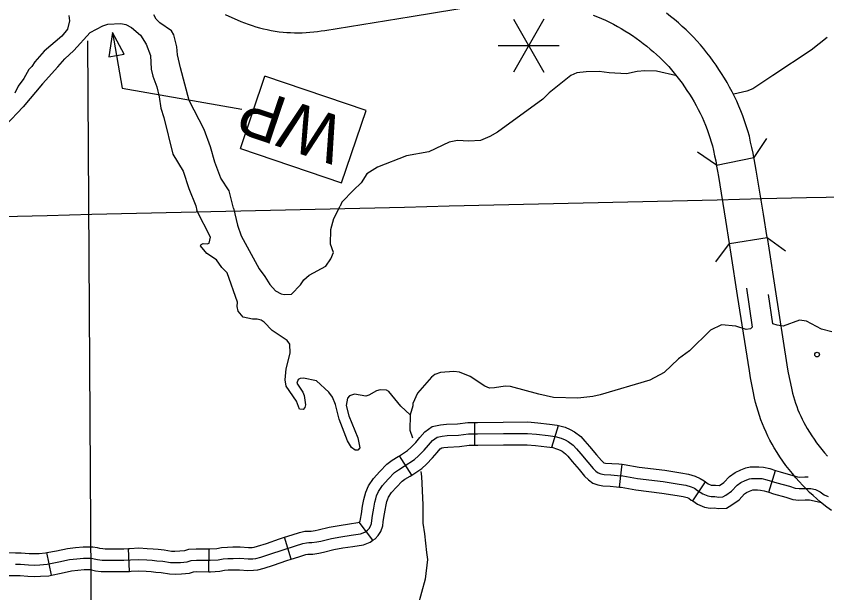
# Model space of a CAD drawing. Extents: x -19 to 366, y -4 to 359.
# Drawn here: x 132.38 to 133.386, y 199.204 to 199.92 of the extents above; entities that cross this region are included whole.
import ezdxf

# ---------------------------------------------------------------- set-up
doc = ezdxf.new("R2010")
doc.units = 0
for name, color, linetype in [('Level 10', 7, 'Continuous'), ('Level 32', 7, 'Continuous'), ('Level 35', 7, 'Continuous'), ('Level 37', 7, 'Continuous'), ('Level 48', 7, 'Continuous'), ('Level 5', 7, 'Continuous'), ('Level 57', 7, 'Continuous'), ('Level 60', 7, 'Continuous'), ('Level 9', 7, 'Continuous')]:
    doc.layers.add(name, color=color, linetype=linetype)

msp = doc.modelspace()

# ---------------------------------------------------------------- linework, layer by layer
at = {"layer": 'Level 10'}
for p, q in [((133.2493, 199.7353), (133.2957, 199.7446)), ((133.2652, 199.6381), (133.312, 199.6454))]:
    msp.add_line(p, q, dxfattribs=at)
for points in [[(132.639, 199.9222), (132.6587, 199.9136), (132.6633, 199.9118), (132.6679, 199.9101), (132.6726, 199.9085), (132.6772, 199.907), (132.682, 199.9057), (132.6867, 199.9045), (132.6915, 199.9034), (132.6963, 199.9024), (132.7012, 199.9016), (132.7061, 199.9008), (132.711, 199.9003), (132.7158, 199.8999), (132.7205, 199.8996), (132.7253, 199.8994), (132.7301, 199.8994), (132.7348, 199.8995), (132.7396, 199.8997), (132.7443, 199.9), (132.7491, 199.9005), (132.7538, 199.901), (132.7585, 199.9017), (132.7628, 199.9024), (132.87, 199.9198), (132.9784, 199.9375)], [(133.0962, 199.9215), (133.1013, 199.9194), (133.1063, 199.9172), (133.1113, 199.9149), (133.1163, 199.9125), (133.1212, 199.91), (133.1261, 199.9074), (133.1309, 199.9047), (133.1356, 199.9018), (133.1403, 199.8989), (133.1449, 199.8959), (133.1494, 199.8927), (133.1539, 199.8895), (133.1583, 199.8862), (133.1627, 199.8827), (133.167, 199.8793), (133.171, 199.8759), (133.1749, 199.8724), (133.1788, 199.8688), (133.1826, 199.8651), (133.1863, 199.8613), (133.1899, 199.8574), (133.1934, 199.8535), (133.1968, 199.8494), (133.2001, 199.8453), (133.2033, 199.8411), (133.2065, 199.8369), (133.2095, 199.8325), (133.2125, 199.8279), (133.2157, 199.8232), (133.2185, 199.8186), (133.2213, 199.8139), (133.224, 199.8092), (133.2265, 199.8044), (133.229, 199.7995), (133.2313, 199.7947), (133.2334, 199.7897), (133.2355, 199.7847), (133.2375, 199.7796), (133.2394, 199.7745), (133.2411, 199.7694), (133.2427, 199.7642), (133.2441, 199.7593), (133.2455, 199.7533), (133.2469, 199.7468), (133.2483, 199.7404), (133.2493, 199.7353)], [(133.2957, 199.7446), (133.2947, 199.75), (133.2932, 199.7569), (133.2916, 199.7638), (133.29, 199.7711), (133.2881, 199.7777), (133.2861, 199.784), (133.2841, 199.7901), (133.2818, 199.7963), (133.2795, 199.8024), (133.277, 199.8084), (133.2743, 199.8144), (133.2715, 199.8203), (133.2686, 199.8262), (133.2655, 199.8319), (133.2623, 199.8376), (133.259, 199.8432), (133.2555, 199.8488), (133.2521, 199.854), (133.2487, 199.8591), (133.245, 199.8644), (133.2412, 199.8695), (133.2373, 199.8746), (133.2333, 199.8796), (133.2292, 199.8845), (133.2249, 199.8893), (133.2206, 199.894), (133.2161, 199.8986), (133.2115, 199.903), (133.2068, 199.9074), (133.202, 199.9117), (133.1971, 199.9158), (133.1922, 199.9197), (133.1872, 199.9237)], [(133.312, 199.6454), (133.3075, 199.6743), (133.2986, 199.729), (133.2974, 199.7361), (133.2961, 199.7431), (133.2957, 199.7446)], [(133.2652, 199.6381), (133.2608, 199.6669), (133.252, 199.7211), (133.2508, 199.7275), (133.2496, 199.734), (133.2493, 199.7353)], [(133.3861, 199.3109), (133.3826, 199.3136), (133.378, 199.3173), (133.3736, 199.3211), (133.3692, 199.325), (133.3649, 199.329), (133.3608, 199.3331), (133.3563, 199.3377), (133.3519, 199.3424), (133.3476, 199.3473), (133.3434, 199.3523), (133.3394, 199.3574), (133.3355, 199.3625), (133.3316, 199.3678), (133.328, 199.3732), (133.3245, 199.3786), (133.321, 199.3843), (133.3183, 199.3891), (133.3156, 199.394), (133.3131, 199.3989), (133.3107, 199.4039), (133.3085, 199.409), (133.3064, 199.4141), (133.3044, 199.4193), (133.3025, 199.4246), (133.3008, 199.4299), (133.2992, 199.4352), (133.2978, 199.4405), (133.2965, 199.446), (133.2946, 199.4545), (133.293, 199.4629), (133.2914, 199.4714), (133.29, 199.4798), (133.2753, 199.5734), (133.2673, 199.6248), (133.2652, 199.6381)], [(133.312, 199.6454), (133.3141, 199.6321), (133.3221, 199.5807), (133.3367, 199.4874), (133.338, 199.4796), (133.3395, 199.4718), (133.341, 199.464), (133.3426, 199.4564), (133.3436, 199.4522), (133.3448, 199.4481), (133.346, 199.4439), (133.3473, 199.4398), (133.3488, 199.4357), (133.3503, 199.4317), (133.352, 199.4277), (133.3538, 199.4237), (133.3556, 199.4198), (133.3576, 199.4159), (133.3596, 199.4121), (133.3618, 199.4084), (133.3645, 199.4039), (133.3674, 199.3994), (133.3704, 199.395), (133.3735, 199.3907), (133.3768, 199.3864), (133.3801, 199.3823), (133.3835, 199.3782), (133.387, 199.3742)], [(133.3919, 199.3066), (133.3861, 199.3109)]]:
    msp.add_lwpolyline(points, dxfattribs=at)
at = {"layer": 'Level 32'}
for p, q in [((132.9493, 199.3876), (132.949, 199.416)), ((133.0449, 199.385), (133.0529, 199.4122)), ((132.871, 199.3506), (132.8555, 199.3744)), ((133.1289, 199.3356), (133.1319, 199.3639)), ((133.314, 199.3293), (133.3224, 199.3564)), ((133.2199, 199.3184), (133.2354, 199.3421)), ((132.8227, 199.2696), (132.8057, 199.2923)), ((132.7213, 199.2462), (132.7128, 199.2733)), ((132.4236, 199.2264), (132.4179, 199.2543)), ((132.5205, 199.231), (132.5192, 199.2594)), ((132.6191, 199.2306), (132.6194, 199.259))]:
    msp.add_line(p, q, dxfattribs=at)
for points in [[(132.8555, 199.3744), (132.8656, 199.381), (132.8695, 199.3846), (132.8758, 199.3909), (132.8808, 199.397), (132.8869, 199.4042), (132.8963, 199.4109), (132.9064, 199.4131), (132.9141, 199.4137), (132.9276, 199.4142), (132.9403, 199.4159), (132.949, 199.416)], [(132.949, 199.416), (132.9524, 199.416), (132.9844, 199.4164), (133.0151, 199.4165), (133.0272, 199.4155), (133.0419, 199.4137), (133.0516, 199.4126), (133.0529, 199.4122)], [(133.0529, 199.4122), (133.0612, 199.4098), (133.0674, 199.4072), (133.0729, 199.4041), (133.0808, 199.3984), (133.0859, 199.3927), (133.0917, 199.386), (133.1004, 199.3755), (133.1064, 199.3685), (133.1084, 199.3664), (133.109, 199.366), (133.1093, 199.3659), (133.1115, 199.3655), (133.1191, 199.3651), (133.1279, 199.3643), (133.1319, 199.3639)], [(132.8212, 199.2943), (132.8223, 199.3003), (132.8237, 199.3095), (132.8251, 199.3168), (132.8263, 199.3212), (132.8271, 199.3248), (132.8297, 199.3301), (132.8346, 199.3377), (132.8417, 199.3453), (132.8496, 199.3536), (132.8543, 199.3572), (132.8615, 199.3614), (132.8744, 199.3698), (132.8793, 199.3744), (132.8863, 199.3814), (132.8916, 199.3878), (132.8966, 199.3936), (132.9022, 199.3977), (132.9085, 199.399), (132.915, 199.3995), (132.9288, 199.4001), (132.9413, 199.4017), (132.9525, 199.4018), (132.9846, 199.4022), (133.0146, 199.4023), (133.0258, 199.4014), (133.0403, 199.3996), (133.0488, 199.3986), (133.0565, 199.3963), (133.0612, 199.3944), (133.0652, 199.3921), (133.0712, 199.3877), (133.0753, 199.3833), (133.0809, 199.3768), (133.0895, 199.3664), (133.0959, 199.3588), (133.0992, 199.3556), (133.1023, 199.3534), (133.1055, 199.3522), (133.1098, 199.3514), (133.1181, 199.351), (133.1264, 199.3502), (133.1328, 199.3495), (133.1512, 199.3465), (133.1832, 199.3424), (133.2027, 199.3394), (133.2112, 199.338), (133.2178, 199.3361), (133.2219, 199.3342), (133.2258, 199.3314), (133.2324, 199.3271), (133.2385, 199.3246), (133.2426, 199.3238), (133.2472, 199.3239), (133.2523, 199.3232), (133.2572, 199.3236), (133.2607, 199.3256), (133.2679, 199.3306), (133.2747, 199.338), (133.2795, 199.3414), (133.2849, 199.3438), (133.2901, 199.3458), (133.2928, 199.3464), (133.2971, 199.3465), (133.301, 199.3464), (133.3057, 199.3461), (133.3118, 199.3448), (133.3243, 199.341), (133.3397, 199.3366), (133.3467, 199.3342), (133.3518, 199.3338), (133.3592, 199.334), (133.3663, 199.334), (133.3722, 199.3327), (133.3779, 199.3297), (133.3828, 199.3261), (133.3878, 199.3241)], [(132.871, 199.3506), (132.8832, 199.3586), (132.8892, 199.3642), (132.8968, 199.3718), (132.9025, 199.3787), (132.9063, 199.3831), (132.9081, 199.3844), (132.9105, 199.3849), (132.9158, 199.3853), (132.93, 199.3859), (132.9423, 199.3875), (132.9493, 199.3876)], [(132.9493, 199.3876), (132.9527, 199.3876), (132.9847, 199.388), (133.014, 199.3881), (133.0244, 199.3872), (133.0386, 199.3855), (133.0459, 199.3847), (133.0449, 199.385)], [(133.0449, 199.385), (133.0518, 199.3829), (133.055, 199.3816), (133.0574, 199.3802), (133.0617, 199.3771), (133.0646, 199.3739), (133.07, 199.3676), (133.0786, 199.3573), (133.0855, 199.3491), (133.0901, 199.3447), (133.0956, 199.3407), (133.1018, 199.3384), (133.1081, 199.3373), (133.117, 199.3368), (133.125, 199.336), (133.1289, 199.3356)], [(132.8057, 199.2923), (132.8063, 199.2928), (132.8067, 199.2932), (132.8069, 199.2935), (132.8071, 199.2959), (132.8083, 199.3026), (132.8097, 199.3119), (132.8112, 199.3201), (132.8126, 199.3247), (132.8137, 199.3295), (132.8173, 199.3371), (132.8234, 199.3464), (132.8314, 199.3551), (132.8401, 199.3642), (132.8464, 199.369), (132.8541, 199.3735), (132.8555, 199.3744)], [(133.1319, 199.3639), (133.1347, 199.3636), (133.1533, 199.3605), (133.1852, 199.3565), (133.205, 199.3535), (133.2144, 199.3518), (133.2228, 199.3494), (133.229, 199.3465), (133.2338, 199.3432), (133.2354, 199.3421)], [(133.2354, 199.3421), (133.239, 199.3397), (133.2427, 199.3382), (133.2437, 199.338), (133.2481, 199.3382), (133.2528, 199.3375), (133.2528, 199.3375), (133.253, 199.3376), (133.2585, 199.3414), (133.2653, 199.3487), (133.2725, 199.3538), (133.2795, 199.3569), (133.2858, 199.3594), (133.2909, 199.3606), (133.2971, 199.3608), (133.3017, 199.3606), (133.3077, 199.3602), (133.3154, 199.3586), (133.3224, 199.3564)], [(133.3224, 199.3564), (133.3283, 199.3546), (133.3439, 199.3502), (133.3497, 199.3482), (133.3521, 199.348), (133.359, 199.3482), (133.363, 199.3482)], [(132.8227, 199.2696), (132.8253, 199.2715), (132.8292, 199.2756), (132.8324, 199.2806), (132.835, 199.2874), (132.8353, 199.2926), (132.8363, 199.2979), (132.8377, 199.3071), (132.8389, 199.3135), (132.8401, 199.3177), (132.8406, 199.32), (132.8421, 199.3231), (132.8459, 199.3289), (132.8521, 199.3356), (132.8591, 199.343), (132.8622, 199.3454), (132.869, 199.3493), (132.871, 199.3506)], [(133.1289, 199.3356), (133.1309, 199.3354), (133.1492, 199.3324), (133.1812, 199.3283), (133.2005, 199.3254), (133.208, 199.3241), (133.2128, 199.3228), (133.2147, 199.3218), (133.2179, 199.3196), (133.2199, 199.3184)], [(133.2199, 199.3184), (133.2257, 199.3145), (133.2344, 199.3109), (133.2414, 199.3095), (133.2464, 199.3097), (133.2518, 199.3089), (133.2615, 199.3096), (133.2684, 199.3136), (133.2772, 199.3198), (133.2841, 199.3272), (133.2866, 199.329), (133.2903, 199.3306), (133.2943, 199.3322), (133.2947, 199.3323), (133.2971, 199.3323), (133.3003, 199.3322), (133.3037, 199.332), (133.3083, 199.331), (133.314, 199.3293)], [(133.314, 199.3293), (133.3202, 199.3273), (133.3354, 199.323), (133.3438, 199.3202), (133.3514, 199.3195), (133.3594, 199.3198), (133.3647, 199.3198), (133.3778, 199.3168)], [(132.3787, 199.24), (132.3852, 199.24), (132.3949, 199.2392), (132.4026, 199.2389), (132.4089, 199.2391), (132.4181, 199.2398), (132.4328, 199.2428), (132.4458, 199.2456), (132.4548, 199.2467), (132.4634, 199.2474), (132.469, 199.2475), (132.4733, 199.2475), (132.4767, 199.2468), (132.4807, 199.2456), (132.4863, 199.2451), (132.4899, 199.245), (132.4974, 199.245), (132.506, 199.2449), (132.5135, 199.2449), (132.5216, 199.2453), (132.5321, 199.2458), (132.5419, 199.2453), (132.5485, 199.2451), (132.5545, 199.2443), (132.5616, 199.2436), (132.5713, 199.2421), (132.5769, 199.2419), (132.5839, 199.2422), (132.592, 199.2429), (132.5969, 199.2447), (132.6035, 199.245), (132.6205, 199.2448), (132.6306, 199.2455), (132.6366, 199.2467), (132.6424, 199.247), (132.6491, 199.2472), (132.6575, 199.2473), (132.6679, 199.2465), (132.6734, 199.2466), (132.6774, 199.247), (132.6834, 199.2485), (132.6948, 199.2522), (132.7112, 199.2579), (132.7265, 199.2627), (132.7355, 199.2655), (132.74, 199.2666), (132.743, 199.2667), (132.7469, 199.2667), (132.7531, 199.2676), (132.758, 199.2685), (132.7712, 199.272), (132.7829, 199.2741), (132.7956, 199.2761), (132.8073, 199.2777), (132.8125, 199.2797), (132.8158, 199.2822), (132.8179, 199.2844), (132.8197, 199.2871), (132.821, 199.2905), (132.8212, 199.2943)], [(132.7128, 199.2733), (132.7223, 199.2762), (132.7316, 199.2791), (132.738, 199.2808), (132.7428, 199.2809), (132.7459, 199.2809), (132.7508, 199.2816), (132.7548, 199.2824), (132.7681, 199.2859), (132.7806, 199.2881), (132.7935, 199.2901), (132.8037, 199.2915), (132.8056, 199.2922), (132.8057, 199.2923)], [(132.6194, 199.259), (132.6201, 199.259), (132.6287, 199.2596), (132.6348, 199.2608), (132.6419, 199.2612), (132.6487, 199.2614), (132.6579, 199.2615), (132.6682, 199.2607), (132.6725, 199.2608), (132.675, 199.261), (132.6794, 199.2622), (132.6903, 199.2657), (132.7067, 199.2714), (132.7128, 199.2733)], [(132.7213, 199.2462), (132.7308, 199.2491), (132.7394, 199.2518), (132.742, 199.2525), (132.7432, 199.2525), (132.7479, 199.2525), (132.7554, 199.2536), (132.7612, 199.2547), (132.7742, 199.2581), (132.7853, 199.2601), (132.7976, 199.262), (132.8108, 199.2638), (132.8194, 199.2671), (132.8227, 199.2696)], [(132.321, 199.2556), (132.3254, 199.2556), (132.3482, 199.2542), (132.3662, 199.2543), (132.3788, 199.2542), (132.3858, 199.2542), (132.3958, 199.2534), (132.4027, 199.2531), (132.4081, 199.2533), (132.4161, 199.2539), (132.4179, 199.2543)], [(132.4179, 199.2543), (132.4298, 199.2567), (132.4435, 199.2596), (132.4533, 199.2608), (132.4628, 199.2616), (132.4689, 199.2617), (132.4747, 199.2617), (132.4801, 199.2606), (132.4833, 199.2597), (132.4871, 199.2593), (132.4902, 199.2592), (132.4974, 199.2592), (132.506, 199.2591), (132.5132, 199.2591), (132.5192, 199.2594)], [(132.5192, 199.2594), (132.521, 199.2595), (132.5321, 199.2601), (132.5425, 199.2595), (132.5497, 199.2592), (132.5561, 199.2584), (132.5634, 199.2577), (132.5726, 199.2562), (132.5768, 199.2561), (132.5829, 199.2564), (132.5889, 199.2569), (132.5941, 199.2588), (132.6033, 199.2592), (132.6194, 199.259)], [(132.6191, 199.2306), (132.6209, 199.2306), (132.6324, 199.2313), (132.6384, 199.2325), (132.643, 199.2328), (132.6494, 199.233), (132.657, 199.2331), (132.6675, 199.2322), (132.6742, 199.2324), (132.6798, 199.2329), (132.6874, 199.2349), (132.6992, 199.2387), (132.7156, 199.2444), (132.7213, 199.2462)], [(132.4236, 199.2264), (132.4357, 199.2289), (132.4482, 199.2316), (132.4562, 199.2326), (132.4641, 199.2332), (132.4691, 199.2333), (132.4719, 199.2333), (132.4733, 199.233), (132.478, 199.2316), (132.4854, 199.231), (132.4897, 199.2308), (132.4973, 199.2308), (132.5059, 199.2307), (132.5138, 199.2307), (132.5205, 199.231)], [(132.3208, 199.2272), (132.3245, 199.2272), (132.3474, 199.2258), (132.3662, 199.2259), (132.3786, 199.2258), (132.3847, 199.2258), (132.394, 199.2251), (132.4025, 199.2247), (132.4097, 199.2249), (132.4201, 199.2257), (132.4236, 199.2264)], [(132.5205, 199.231), (132.5223, 199.2311), (132.5321, 199.2316), (132.5412, 199.2311), (132.5474, 199.2309), (132.5529, 199.2302), (132.5598, 199.2295), (132.5699, 199.2279), (132.577, 199.2277), (132.5848, 199.228), (132.595, 199.2289), (132.5997, 199.2306), (132.6038, 199.2308), (132.6191, 199.2306)]]:
    msp.add_lwpolyline(points, dxfattribs=at)
at = {"layer": 'Level 35'}
for points in [[(132.3956, 199.8538), (132.389, 199.8427), (132.3823, 199.8332), (132.3779, 199.8247)], [(132.4125, 199.8362), (132.3884, 199.8074), (132.3664, 199.7844), (132.3471, 199.7583), (132.3316, 199.7346), (132.314, 199.7165), (132.3051, 199.7057), (132.2812, 199.6857), (132.2703, 199.6779), (132.2662, 199.676), (132.2571, 199.6743), (132.2496, 199.6716)], [(132.869, 199.4255), (132.8685, 199.4061), (132.8716, 199.3967)], [(132.882, 199.355), (132.883, 199.3487), (132.8847, 199.3138), (132.8847, 199.2907), (132.8868, 199.2778), (132.8891, 199.2544), (132.8904, 199.2457), (132.8877, 199.2213), (132.8784, 199.1882), (132.8782, 199.1825), (132.8809, 199.1761), (132.878, 199.1666), (132.8537, 199.1279), (132.8467, 199.1141), (132.8417, 199.1004), (132.8306, 199.0827), (132.808, 199.0524), (132.8037, 199.0429), (132.7962, 199.0143), (132.7863, 198.9933), (132.7837, 198.9689), (132.7846, 198.9591), (132.7873, 198.9458)]]:
    msp.add_lwpolyline(points, dxfattribs=at)
at = {"layer": 'Level 37'}
for points in [[(133.3115, 199.7682), (133.2957, 199.7446)], [(133.2493, 199.7353), (133.2257, 199.7511)], [(133.2485, 199.6152), (133.2652, 199.6381)], [(133.312, 199.6454), (133.335, 199.6287)]]:
    msp.add_lwpolyline(points, dxfattribs=at)
at = {"layer": 'Level 48'}
for p, q in [((133.035, 199.9163), (132.9971, 199.8507)), ((132.9971, 199.9163), (133.035, 199.8507)), ((132.9782, 199.8835), (133.054, 199.8835))]:
    msp.add_line(p, q, dxfattribs=at)
at = {"layer": 'Level 5'}
msp.add_lwpolyline([(132.4737, 199.0864), (132.4687, 199.8893)], dxfattribs=at)
at = {"layer": 'Level 57'}
for p, q in [((132.6582, 199.7558), (132.6886, 199.8455)), ((132.8142, 199.8029), (132.6886, 199.8455)), ((132.7838, 199.7132), (132.8142, 199.8029)), ((132.6582, 199.7558), (132.7838, 199.7132))]:
    msp.add_line(p, q, dxfattribs=at)
msp.add_lwpolyline([(132.4947, 199.8694), (132.5137, 199.8728), (132.4992, 199.8997)], close=True, dxfattribs=at)
msp.add_lwpolyline([(132.4992, 199.8997), (132.5113, 199.8306), (132.6598, 199.8046)], dxfattribs=at)
msp.add_circle((133.3741, 199.5001), 0.00284, dxfattribs=at)
at = {"layer": 'Level 60'}
for points in [[(139.4406, 1.5315), (139.2511, 10.1473), (139.0608, 18.7633), (138.8699, 27.3793), (138.6784, 35.9956), (138.4861, 44.6119), (138.2932, 53.2285), (138.0997, 61.8451), (137.9055, 70.4619), (137.7106, 79.0789), (137.5151, 87.6959), (137.319, 96.3132), (137.1221, 104.9306), (136.9247, 113.5481), (136.7265, 122.1658), (136.5278, 130.7836), (136.3283, 139.4016), (136.1282, 148.0197), (135.9275, 156.6379), (135.7261, 165.2564), (135.5241, 173.8749), (135.3214, 182.4936), (135.1181, 191.1125), (134.9141, 199.7315), (134.7095, 208.3506), (134.5043, 216.9699), (134.2984, 225.5894), (134.0919, 234.209), (133.8847, 242.8288), (133.6769, 251.4487), (133.4685, 260.0687), (133.2594, 268.6889), (133.0497, 277.3093), (132.8393, 285.9298), (132.6283, 294.5504), (132.4167, 303.1713), (132.2044, 311.7922), (131.9916, 320.4133), (131.778, 329.0346), (131.5639, 337.656), (131.3491, 346.2776)], [(0, 198.1326), (7.1014, 198.137), (14.2028, 198.1503), (21.3042, 198.1724), (28.4055, 198.2034), (35.5068, 198.2433), (42.6081, 198.292), (49.7092, 198.3496), (56.8103, 198.4161), (63.9113, 198.4913), (71.0123, 198.5755), (78.1131, 198.6685), (85.2137, 198.7704), (92.3143, 198.8811), (99.4147, 199.0007), (106.5149, 199.1291), (113.615, 199.2664), (120.7149, 199.4126), (127.8146, 199.5676), (134.9141, 199.7315), (142.0135, 199.9042), (149.1125, 200.0858), (156.2114, 200.2762), (163.31, 200.4755), (170.4084, 200.6837), (177.5065, 200.9007), (184.6043, 201.1265), (191.7018, 201.3612), (198.799, 201.6048), (205.896, 201.8572), (212.9926, 202.1185), (220.0888, 202.3886), (227.1848, 202.6676), (234.2803, 202.9554), (241.3755, 203.2521), (248.4704, 203.5576), (255.5648, 203.872), (262.6589, 204.1952), (269.7525, 204.5273), (276.8457, 204.8682), (283.9385, 205.218), (291.0309, 205.5766), (298.1228, 205.9441), (305.2142, 206.3204), (312.3051, 206.7056), (319.3956, 207.0996), (326.4856, 207.5024), (333.5751, 207.9141), (340.664, 208.3347)], [(0, 189.5162), (7.1121, 189.5206), (14.2243, 189.5339), (21.3364, 189.556), (28.4484, 189.5869), (35.5605, 189.6267), (42.6725, 189.6754), (49.7844, 189.7329), (56.8962, 189.7992), (64.0079, 189.8744), (71.1196, 189.9584), (78.2311, 190.0512), (85.3425, 190.1529), (92.4538, 190.2635), (99.5649, 190.3829), (106.6759, 190.5111), (113.7867, 190.6482), (120.8974, 190.7941), (128.0078, 190.9489), (135.1181, 191.1125), (142.2282, 191.2849), (149.338, 191.4662), (156.4476, 191.6563), (163.5569, 191.8553), (170.666, 192.0631), (177.7749, 192.2798), (184.8835, 192.5053), (191.9917, 192.7396), (199.0997, 192.9828), (206.2074, 193.2348), (213.3147, 193.4956), (220.4218, 193.7653), (227.5285, 194.0438), (234.6348, 194.3312), (241.7408, 194.6274), (248.8464, 194.9324), (255.9516, 195.2463), (263.0564, 195.569), (270.1608, 195.9005), (277.2648, 196.2409), (284.3683, 196.5901), (291.4715, 196.9481), (298.5741, 197.315), (305.6763, 197.6907), (312.7781, 198.0753), (319.8793, 198.4686), (326.9801, 198.8708), (334.0804, 199.2818), (341.1801, 199.7017)]]:
    msp.add_spline(points, degree=3, dxfattribs=at)
at = {"layer": 'Level 9'}
for points in [[(132.4449, 199.9209), (132.4458, 199.9141), (132.4433, 199.9038), (132.4362, 199.8954), (132.4146, 199.8765), (132.403, 199.8634), (132.3993, 199.8577), (132.3956, 199.8538)], [(132.6496, 199.6817), (132.6443, 199.7033), (132.6339, 199.7191), (132.6264, 199.7387), (132.6211, 199.758), (132.6132, 199.7795), (132.5945, 199.8156), (132.5837, 199.8561), (132.58, 199.872), (132.5791, 199.8822), (132.5755, 199.8969), (132.5724, 199.9018), (132.5582, 199.9119), (132.5536, 199.9164), (132.5505, 199.9216)], [(132.4125, 199.8362), (132.4315, 199.857), (132.4401, 199.8673), (132.4513, 199.8774), (132.4714, 199.8997), (132.4871, 199.9082), (132.4935, 199.9102), (132.5098, 199.9108), (132.5159, 199.9098), (132.5227, 199.9061), (132.5339, 199.8964), (132.5412, 199.8855), (132.5464, 199.8711), (132.5474, 199.8541), (132.5494, 199.8457), (132.5545, 199.8325), (132.5574, 199.8201), (132.5591, 199.806), (132.5631, 199.7943), (132.574, 199.7486), (132.5872, 199.7279), (132.5939, 199.706), (132.6026, 199.6845), (132.6038, 199.6788)], [(133.3867, 199.8936), (133.3669, 199.8777)], [(133.3669, 199.8777), (133.3193, 199.8463), (133.2942, 199.83), (133.2867, 199.8269), (133.2707, 199.8234)], [(133.2, 199.8462), (133.1746, 199.8519), (133.1602, 199.8524), (133.1508, 199.8515), (133.1376, 199.8487), (133.116, 199.8499), (133.1035, 199.8513), (133.0876, 199.851), (133.0759, 199.8497), (133.0684, 199.8466), (133.0414, 199.825), (133.0336, 199.8169), (132.9774, 199.7763), (132.9677, 199.7708), (132.956, 199.7657), (132.9417, 199.7648), (132.9276, 199.7657), (132.9174, 199.7637), (132.8919, 199.7515), (132.8643, 199.7466), (132.8282, 199.7328), (132.8151, 199.7243), (132.8081, 199.7132), (132.7984, 199.7043)], [(132.7984, 199.7043), (132.7842, 199.6893), (132.782, 199.6844)], [(132.6119, 199.6378), (132.6168, 199.6375), (132.6195, 199.6383), (132.6209, 199.6459), (132.6038, 199.6788)], [(132.6496, 199.6817), (132.6543, 199.6608), (132.659, 199.6473), (132.6812, 199.6067), (132.6885, 199.5969), (132.6948, 199.5872), (132.7017, 199.5793), (132.7089, 199.5753), (132.7123, 199.5746), (132.7214, 199.5751), (132.7329, 199.5867), (132.737, 199.5928), (132.7433, 199.5986), (132.7643, 199.6099), (132.7702, 199.6188), (132.7735, 199.6268), (132.7699, 199.6373), (132.7704, 199.6552), (132.7743, 199.6689), (132.782, 199.6844)], [(132.869, 199.4255), (132.8571, 199.4359), (132.8424, 199.4542), (132.8394, 199.4561), (132.8318, 199.4563), (132.8269, 199.4551), (132.8175, 199.4496), (132.8138, 199.4484), (132.7998, 199.4509), (132.7937, 199.4489), (132.7911, 199.4462), (132.7894, 199.437), (132.7926, 199.4242), (132.804, 199.3967), (132.8065, 199.3842), (132.8039, 199.3815), (132.8005, 199.3815), (132.7959, 199.3848), (132.7912, 199.3931), (132.7806, 199.4198), (132.7761, 199.438), (132.7726, 199.4474), (132.768, 199.4534), (132.7526, 199.4675), (132.7363, 199.471), (132.7322, 199.4706), (132.7299, 199.469), (132.7281, 199.4645), (132.7355, 199.4536), (132.7374, 199.4491), (132.7391, 199.4377), (132.738, 199.4343), (132.7362, 199.432), (132.7313, 199.4323), (132.7277, 199.4421), (132.7149, 199.4608), (132.7137, 199.4688), (132.715, 199.4824), (132.7199, 199.5019), (132.7194, 199.5132), (132.7163, 199.5174), (132.6976, 199.5299), (132.6876, 199.5404), (132.6837, 199.5426), (132.6788, 199.544), (132.6731, 199.544), (132.6614, 199.5464), (132.6552, 199.5539), (132.654, 199.5596), (132.6543, 199.5653), (132.6416, 199.6015), (132.6351, 199.6082), (132.6285, 199.6175), (132.6166, 199.6257), (132.6086, 199.635), (132.6093, 199.6366), (132.6119, 199.6378)], [(133.2864, 199.5826), (133.2936, 199.5341), (133.2914, 199.5322), (133.2861, 199.5313), (133.2732, 199.5353), (133.2554, 199.5369), (133.2419, 199.5302), (133.2155, 199.5048), (133.202, 199.4947), (133.1841, 199.4777), (133.1665, 199.4683), (133.1048, 199.4502), (133.0958, 199.4482), (133.0769, 199.446), (133.047, 199.447)], [(133.3924, 199.5282), (133.3795, 199.5317), (133.3608, 199.5417), (133.3524, 199.5427), (133.3321, 199.5355), (133.3246, 199.5365), (133.3192, 199.5383), (133.3139, 199.5748)], [(133.047, 199.447), (133.0288, 199.4509), (132.9935, 199.4605), (132.9867, 199.4608), (132.9735, 199.4587), (132.9675, 199.4586), (132.9614, 199.4607), (132.9434, 199.473), (132.9301, 199.4784), (132.9233, 199.4791), (132.9067, 199.4777), (132.8995, 199.4753), (132.8954, 199.4722), (132.878, 199.4521), (132.8721, 199.4392), (132.8722, 199.4365), (132.869, 199.4255)]]:
    msp.add_lwpolyline(points, dxfattribs=at)

# ---------------------------------------------------------------- texts
at = {"layer": 'Level 57'}
msp.add_text('WP', height=0.06, rotation=161.2725, dxfattribs=at).set_placement((132.7914, 199.7923))

doc.saveas('drawing.dxf')
